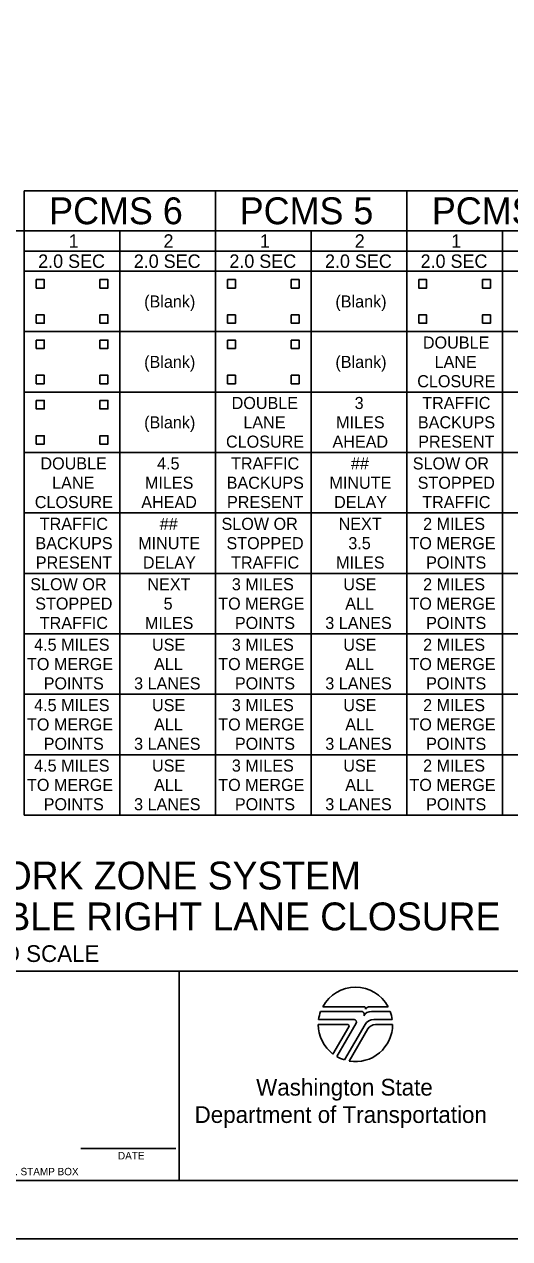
# Model space of a CAD drawing. Extents: x 99999.1 to 100055.7, y 99995 to 100017.5.
# Drawn here: x 100029.47 to 100032.09, y 99999.69 to 100006.22 of the extents above; entities that cross this region are included whole.
import ezdxf

# ---------------------------------------------------------------- set-up
doc = ezdxf.new("R2010")
doc.units = 0
for name, color, linetype in [('SH_DE_DetailHeading1Text', 7, 'Continuous'), ('SH_DE_DetailHeading3Text', 7, 'Continuous'), ('SH_GI_PlotLimits', 7, 'Continuous'), ('SH_GI_SheetBorder', 7, 'Continuous'), ('SH_GI_SheetTextInCells', 7, 'Continuous'), ('SH_GI_WSDOTLogo', 7, 'Continuous'), ('TR_WZ_WorkZoneDetails', 7, 'Continuous'), ('TR_WZ_WorkZoneTextCurrent', 7, 'Continuous')]:
    doc.layers.add(name, color=color, linetype=linetype)

msp = doc.modelspace()

# ---------------------------------------------------------------- linework, layer by layer
at = {"layer": 'SH_GI_PlotLimits'}
msp.add_lwpolyline([(100019.0625, 99999.6875), (100036.0625, 99999.6875), (100036.0625, 100010.6875), (100019.0625, 100010.6875)], close=True, dxfattribs=at)
at = {"layer": 'SH_GI_SheetBorder'}
for p, q in [((100020, 100001.1259), (100035.75, 100001.1259)), ((100030.3089, 100001.1259), (100030.3089, 100000)), ((100029.7797, 100000.1733), (100030.2914, 100000.1733)), ((100020, 100000), (100035.75, 100000))]:
    msp.add_line(p, q, dxfattribs=at)
at = {"layer": 'SH_GI_WSDOTLogo'}
for p, q in [((100031.303, 100000.9354), (100031.0815, 100000.9354)), ((100031.433, 100000.9354), (100031.3351, 100000.9354)), ((100031.059, 100000.8661), (100031.2496, 100000.8661)), ((100031.2894, 100000.9094), (100031.0697, 100000.9094)), ((100031.343, 100000.9094), (100031.3429, 100000.9094)), ((100031.4448, 100000.9094), (100031.343, 100000.9094)), ((100031.3558, 100000.8661), (100031.4555, 100000.8661)), ((100031.0572, 100000.84), (100031.2148, 100000.84)), ((100031.222, 100000.8277), (100031.1364, 100000.6807)), ((100031.261, 100000.8464), (100031.1567, 100000.6672)), ((100031.1989, 100000.6487), (100031.3089, 100000.839)), ((100031.2244, 100000.6428), (100031.3242, 100000.8156)), ((100031.3655, 100000.8394), (100031.4572, 100000.8394))]:
    msp.add_line(p, q, dxfattribs=at)
for centre, radius, start, end in [((100031.2572, 100000.84), 0.2, 28.47865, 151.53204), ((100031.303, 100000.9263), 0.00903, 329.87418, 90.00328), ((100031.3352, 100000.9066), 0.0287, 90.00721, 148.16763), ((100031.2572, 100000.84), 0.2, 159.69598, 172.50569), ((100031.2497, 100000.853), 0.0131, 329.76834, 90), ((100031.2894, 100000.8946), 0.0148, 327.8418, 89.99855), ((100031.3429, 100000.861), 0.0484, 89.99529, 147.82376), ((100031.3558, 100000.8119), 0.0542, 90, 149.99738), ((100031.2572, 100000.84), 0.2, 7.49431, 20.29406), ((100031.2572, 100000.84), 0.2, 179.99864, 232.84327), ((100031.2149, 100000.8318), 0.0082, 329.74356, 90), ((100031.2572, 100000.84), 0.2, 260.54554, 359.80857), ((100031.3654, 100000.7918), 0.0476, 90, 150.05432), ((100031.2572, 100000.84), 0.2, 239.79292, 253.0448)]:
    msp.add_arc(centre, radius, start, end, dxfattribs=at)
at = {"layer": 'TR_WZ_WorkZoneDetails'}
for p, q in [((100029.475, 100005.3241), (100029.475, 100004.9991)), ((100029.475, 100005.3241), (100030.5042, 100005.3241)), ((100030.5042, 100005.3241), (100031.5333, 100005.3241)), ((100030.5042, 100005.3241), (100030.5042, 100004.9991)), ((100031.5333, 100005.3241), (100032.5625, 100005.3241)), ((100031.5333, 100005.3241), (100031.5333, 100004.9991)), ((100031.5333, 100005.3241), (100031.5333, 100004.9991)), ((100029.475, 100005.1075), (100029.475, 100004.9991)), ((100029.9896, 100005.1075), (100029.9896, 100004.9991)), ((100031.0187, 100005.1075), (100031.0187, 100004.9991)), ((100032.0479, 100005.1075), (100032.0479, 100004.9991)), ((100029.475, 100004.9991), (100029.475, 100004.8908)), ((100029.9896, 100004.9991), (100029.9896, 100004.8908)), ((100030.5042, 100004.9991), (100030.5042, 100004.8908)), ((100031.0187, 100004.9991), (100031.0187, 100004.8908)), ((100031.5333, 100004.9991), (100031.5333, 100004.8908)), ((100031.5333, 100004.9991), (100031.5333, 100004.8908)), ((100032.0479, 100004.9991), (100032.0479, 100004.8908)), ((100029.475, 100004.8908), (100029.475, 100004.5658)), ((100030.5042, 100004.8908), (100029.475, 100004.8908)), ((100029.9896, 100004.8908), (100029.9896, 100004.5658)), ((100030.5042, 100004.8908), (100030.5042, 100004.5658)), ((100031.5333, 100004.8908), (100030.5042, 100004.8908)), ((100031.0187, 100004.8908), (100031.0187, 100004.5658)), ((100031.5333, 100004.8908), (100031.5333, 100004.5658)), ((100031.5333, 100004.8908), (100031.5333, 100004.5658)), ((100032.5625, 100004.8908), (100031.5333, 100004.8908)), ((100032.0479, 100004.8908), (100032.0479, 100004.5658)), ((100029.475, 100004.5658), (100029.475, 100004.2408)), ((100030.5042, 100004.5658), (100029.475, 100004.5658)), ((100029.9896, 100004.5658), (100029.9896, 100004.2408)), ((100030.5042, 100004.5658), (100030.5042, 100004.2408)), ((100031.5333, 100004.5658), (100030.5042, 100004.5658)), ((100031.0187, 100004.5658), (100031.0187, 100004.2408)), ((100031.5333, 100004.5658), (100031.5333, 100004.2408)), ((100032.5625, 100004.5658), (100031.5333, 100004.5658)), ((100031.5333, 100004.5658), (100031.5333, 100004.2408)), ((100032.0479, 100004.5658), (100032.0479, 100004.2408)), ((100029.475, 100004.2408), (100029.475, 100003.9158)), ((100030.5042, 100004.2408), (100029.475, 100004.2408)), ((100030.5042, 100004.2408), (100029.475, 100004.2408)), ((100029.9896, 100004.2408), (100029.9896, 100003.9158)), ((100030.5042, 100004.2408), (100030.5042, 100003.9158)), ((100031.5333, 100004.2408), (100030.5042, 100004.2408)), ((100031.5333, 100004.2408), (100030.5042, 100004.2408)), ((100031.0187, 100004.2408), (100031.0187, 100003.9158)), ((100031.5333, 100004.2408), (100031.5333, 100003.9158)), ((100032.5625, 100004.2408), (100031.5333, 100004.2408)), ((100032.5625, 100004.2408), (100031.5333, 100004.2408)), ((100031.5333, 100004.2408), (100031.5333, 100003.9158)), ((100032.0479, 100004.2408), (100032.0479, 100003.9158)), ((100029.475, 100003.9158), (100029.475, 100003.5908)), ((100030.5042, 100003.9158), (100029.475, 100003.9158)), ((100029.9896, 100003.9158), (100029.9896, 100003.5908)), ((100030.5042, 100003.9158), (100030.5042, 100003.5908)), ((100031.5333, 100003.9158), (100030.5042, 100003.9158)), ((100031.0187, 100003.9158), (100031.0187, 100003.5908)), ((100031.5333, 100003.9158), (100031.5333, 100003.5908)), ((100032.5625, 100003.9158), (100031.5333, 100003.9158)), ((100031.5333, 100003.9158), (100031.5333, 100003.5908)), ((100032.0479, 100003.9158), (100032.0479, 100003.5908)), ((100029.475, 100003.5908), (100029.475, 100003.2658)), ((100030.5042, 100003.5908), (100029.475, 100003.5908)), ((100029.9896, 100003.5908), (100029.9896, 100003.2658)), ((100030.5042, 100003.5908), (100030.5042, 100003.2658)), ((100031.5333, 100003.5908), (100030.5042, 100003.5908)), ((100031.0187, 100003.5908), (100031.0187, 100003.2658)), ((100031.5333, 100003.5908), (100031.5333, 100003.2658)), ((100032.5625, 100003.5908), (100031.5333, 100003.5908)), ((100031.5333, 100003.5908), (100031.5333, 100003.2658)), ((100032.0479, 100003.5908), (100032.0479, 100003.2658)), ((100029.475, 100003.2658), (100029.475, 100002.9408)), ((100030.5042, 100003.2658), (100029.475, 100003.2658)), ((100029.9896, 100003.2658), (100029.9896, 100002.9408)), ((100030.5042, 100003.2658), (100030.5042, 100002.9408)), ((100031.5333, 100003.2658), (100030.5042, 100003.2658)), ((100031.0187, 100003.2658), (100031.0187, 100002.9408)), ((100031.5333, 100003.2658), (100031.5333, 100002.9408)), ((100032.5625, 100003.2658), (100031.5333, 100003.2658)), ((100031.5333, 100003.2658), (100031.5333, 100002.9408)), ((100032.0479, 100003.2658), (100032.0479, 100002.9408)), ((100029.475, 100002.9408), (100029.475, 100002.6158)), ((100030.5042, 100002.9408), (100029.475, 100002.9408)), ((100029.9896, 100002.9408), (100029.9896, 100002.6158)), ((100031.5333, 100002.9408), (100030.5042, 100002.9408)), ((100030.5042, 100002.9408), (100030.5042, 100002.6158)), ((100031.0187, 100002.9408), (100031.0187, 100002.6158)), ((100032.5625, 100002.9408), (100031.5333, 100002.9408)), ((100031.5333, 100002.9408), (100031.5333, 100002.6158)), ((100031.5333, 100002.9408), (100031.5333, 100002.6158)), ((100032.0479, 100002.9408), (100032.0479, 100002.6158)), ((100030.5042, 100002.6158), (100029.475, 100002.6158)), ((100029.475, 100002.6158), (100029.475, 100002.2908)), ((100030.5042, 100002.6158), (100029.475, 100002.6158)), ((100029.9896, 100002.6158), (100029.9896, 100002.2908)), ((100031.5333, 100002.6158), (100030.5042, 100002.6158)), ((100031.5333, 100002.6158), (100030.5042, 100002.6158)), ((100030.5042, 100002.6158), (100030.5042, 100002.2908)), ((100031.0187, 100002.6158), (100031.0187, 100002.2908)), ((100032.5625, 100002.6158), (100031.5333, 100002.6158)), ((100032.5625, 100002.6158), (100031.5333, 100002.6158)), ((100031.5333, 100002.6158), (100031.5333, 100002.2908)), ((100031.5333, 100002.6158), (100031.5333, 100002.2908)), ((100032.0479, 100002.6158), (100032.0479, 100002.2908)), ((100029.475, 100002.2908), (100029.475, 100001.9658)), ((100030.5042, 100002.2908), (100029.475, 100002.2908)), ((100029.9896, 100002.2908), (100029.9896, 100001.9658)), ((100030.5042, 100002.2908), (100030.5042, 100001.9658)), ((100031.5333, 100002.2908), (100030.5042, 100002.2908)), ((100031.0187, 100002.2908), (100031.0187, 100001.9658)), ((100031.5333, 100002.2908), (100031.5333, 100001.9658)), ((100031.5333, 100002.2908), (100031.5333, 100001.9658)), ((100032.5625, 100002.2908), (100031.5333, 100002.2908)), ((100032.0479, 100002.2908), (100032.0479, 100001.9658)), ((100030.5042, 100001.9658), (100029.475, 100001.9658)), ((100031.5333, 100001.9658), (100030.5042, 100001.9658)), ((100032.5625, 100001.9658), (100031.5333, 100001.9658))]:
    msp.add_line(p, q, dxfattribs=at)
for points in [[(100028.4458, 100005.1075), (100029.475, 100005.1075)], [(100029.475, 100005.1075), (100030.5042, 100005.1075)], [(100030.5042, 100005.1075), (100031.5333, 100005.1075)], [(100031.5333, 100005.1075), (100032.5625, 100005.1075)], [(100029.475, 100004.9991), (100030.5042, 100004.9991)], [(100030.5042, 100004.9991), (100031.5333, 100004.9991)], [(100031.5333, 100004.9991), (100032.5625, 100004.9991)]]:
    msp.add_lwpolyline(points, dxfattribs=at)
at = {"layer": 'TR_WZ_WorkZoneTextCurrent'}
for points in [[(100029.5393, 100004.8456), (100029.5822, 100004.8456), (100029.5822, 100004.8005), (100029.5393, 100004.8005)], [(100029.8824, 100004.8456), (100029.9253, 100004.8456), (100029.9253, 100004.8005), (100029.8824, 100004.8005)], [(100030.5685, 100004.8456), (100030.6114, 100004.8456), (100030.6114, 100004.8005), (100030.5685, 100004.8005)], [(100030.9115, 100004.8456), (100030.9544, 100004.8456), (100030.9544, 100004.8005), (100030.9115, 100004.8005)], [(100031.5977, 100004.8456), (100031.6405, 100004.8456), (100031.6405, 100004.8005), (100031.5977, 100004.8005)], [(100031.9407, 100004.8456), (100031.9836, 100004.8456), (100031.9836, 100004.8005), (100031.9407, 100004.8005)], [(100029.5393, 100004.6109), (100029.5822, 100004.6109), (100029.5822, 100004.6561), (100029.5393, 100004.6561)], [(100029.8824, 100004.6109), (100029.9253, 100004.6109), (100029.9253, 100004.6561), (100029.8824, 100004.6561)], [(100030.5685, 100004.6109), (100030.6114, 100004.6109), (100030.6114, 100004.6561), (100030.5685, 100004.6561)], [(100030.9115, 100004.6109), (100030.9544, 100004.6109), (100030.9544, 100004.6561), (100030.9115, 100004.6561)], [(100031.5977, 100004.6109), (100031.6405, 100004.6109), (100031.6405, 100004.6561), (100031.5977, 100004.6561)], [(100031.9407, 100004.6109), (100031.9836, 100004.6109), (100031.9836, 100004.6561), (100031.9407, 100004.6561)], [(100029.5393, 100004.5206), (100029.5822, 100004.5206), (100029.5822, 100004.4755), (100029.5393, 100004.4755)], [(100029.8824, 100004.5206), (100029.9253, 100004.5206), (100029.9253, 100004.4755), (100029.8824, 100004.4755)], [(100030.5685, 100004.5206), (100030.6114, 100004.5206), (100030.6114, 100004.4755), (100030.5685, 100004.4755)], [(100030.9115, 100004.5206), (100030.9544, 100004.5206), (100030.9544, 100004.4755), (100030.9115, 100004.4755)], [(100029.5393, 100004.2859), (100029.5822, 100004.2859), (100029.5822, 100004.3311), (100029.5393, 100004.3311)], [(100029.8824, 100004.2859), (100029.9253, 100004.2859), (100029.9253, 100004.3311), (100029.8824, 100004.3311)], [(100030.5685, 100004.2859), (100030.6114, 100004.2859), (100030.6114, 100004.3311), (100030.5685, 100004.3311)], [(100030.9115, 100004.2859), (100030.9544, 100004.2859), (100030.9544, 100004.3311), (100030.9115, 100004.3311)], [(100029.5393, 100004.1956), (100029.5822, 100004.1956), (100029.5822, 100004.1505), (100029.5393, 100004.1505)], [(100029.8824, 100004.1956), (100029.9253, 100004.1956), (100029.9253, 100004.1505), (100029.8824, 100004.1505)], [(100029.5393, 100003.9609), (100029.5822, 100003.9609), (100029.5822, 100004.0061), (100029.5393, 100004.0061)], [(100029.8824, 100003.9609), (100029.9253, 100003.9609), (100029.9253, 100004.0061), (100029.8824, 100004.0061)]]:
    msp.add_lwpolyline(points, close=True, dxfattribs=at)

# ---------------------------------------------------------------- texts
at = {"layer": 'SH_DE_DetailHeading1Text'}
for s, p in [('9-MILE SMART WORK ZONE SYSTEM', (100027.7097, 100001.5658)), ('FREEWAY (3 LANES): DOUBLE RIGHT LANE CLOSURE', (100026.81, 100001.3458))]:
    msp.add_text(s, height=0.15, dxfattribs=at).set_placement(p)
at = {"layer": 'SH_DE_DetailHeading3Text'}
msp.add_text('NOT TO SCALE', height=0.09, dxfattribs=at).set_placement((100028.9969, 100001.1759))
at = {"layer": 'SH_GI_SheetTextInCells'}
for s, height, p in [('Washington State', 0.090072, (100030.7229, 100000.4571)), ('Department of Transportation', 0.090072, (100030.3916, 100000.3101)), ('DATE', 0.04003, (100029.9794, 100000.1141)), ('P.E. STAMP BOX', 0.040032, (100029.339, 100000.0286))]:
    msp.add_text(s, height=height, dxfattribs=at).set_placement(p)
at = {"layer": 'TR_WZ_WorkZoneTextCurrent'}
for s, height, p in [('PCMS 6', 0.14444, (100029.6091, 100005.1436)), ('PCMS 5', 0.14444, (100030.6345, 100005.1436)), ('PCMS 4', 0.14444, (100031.6687, 100005.1436)), ('1', 0.0722, (100029.7142, 100005.0172)), ('2', 0.0722, (100030.2242, 100005.0172)), ('1', 0.0722, (100030.7433, 100005.0172)), ('2', 0.0722, (100031.2534, 100005.0172)), ('1', 0.0722, (100031.7725, 100005.0172)), ('2.0 SEC', 0.07222, (100029.5497, 100004.9088)), ('2.0 SEC', 0.07222, (100030.0643, 100004.9088)), ('2.0 SEC', 0.07222, (100030.5788, 100004.9088)), ('2.0 SEC', 0.07222, (100031.0934, 100004.9088)), ('2.0 SEC', 0.07222, (100031.608, 100004.9088)), ('(Blank)', 0.065, (100030.1202, 100004.6958)), ('(Blank)', 0.065, (100031.1494, 100004.6958)), ('DOUBLE', 0.065, (100031.6203, 100004.4748)), ('(Blank)', 0.065, (100030.1202, 100004.3708)), ('(Blank)', 0.065, (100031.1494, 100004.3708)), ('LANE', 0.065, (100031.6832, 100004.3708)), ('CLOSURE', 0.065, (100031.59, 100004.2668)), ('DOUBLE', 0.065, (100030.5911, 100004.1498)), ('3', 0.065, (100031.253, 100004.1498)), ('TRAFFIC', 0.065, (100031.6168, 100004.1498)), ('(Blank)', 0.065, (100030.1202, 100004.0458)), ('LANE', 0.065, (100030.654, 100004.0458)), ('MILES', 0.065, (100031.1534, 100004.0458)), ('BACKUPS', 0.065, (100031.5935, 100004.0458)), ('CLOSURE', 0.065, (100030.5608, 100003.9418)), ('AHEAD', 0.065, (100031.1337, 100003.9418)), ('PRESENT', 0.065, (100031.5952, 100003.9418)), ('DOUBLE', 0.065, (100029.5619, 100003.8248)), ('4.5', 0.065, (100030.1899, 100003.8248)), ('TRAFFIC', 0.065, (100030.5877, 100003.8248)), ('##', 0.065, (100031.2332, 100003.8248)), ('SLOW OR', 0.065, (100031.5657, 100003.8248)), ('LANE', 0.065, (100029.6248, 100003.7208)), ('MILES', 0.065, (100030.1243, 100003.7208)), ('BACKUPS', 0.065, (100030.5643, 100003.7208)), ('MINUTE', 0.065, (100031.1174, 100003.7208)), ('STOPPED', 0.065, (100031.5923, 100003.7208)), ('CLOSURE', 0.065, (100029.5317, 100003.6168)), ('AHEAD', 0.065, (100030.1045, 100003.6168)), ('PRESENT', 0.065, (100030.566, 100003.6168)), ('DELAY', 0.065, (100031.1424, 100003.6168)), ('TRAFFIC', 0.065, (100031.6168, 100003.6168)), ('TRAFFIC', 0.065, (100029.5585, 100003.4998)), ('##', 0.065, (100030.2041, 100003.4998)), ('SLOW OR', 0.065, (100030.5365, 100003.4998)), ('NEXT', 0.065, (100031.1668, 100003.4998)), ('2 MILES', 0.065, (100031.6214, 100003.4998)), ('BACKUPS', 0.065, (100029.5351, 100003.3958)), ('MINUTE', 0.065, (100030.0882, 100003.3958)), ('STOPPED', 0.065, (100030.5631, 100003.3958)), ('3.5', 0.065, (100031.219, 100003.3958)), ('TO MERGE', 0.065, (100031.5481, 100003.3958)), ('PRESENT', 0.065, (100029.5369, 100003.2918)), ('DELAY', 0.065, (100030.1132, 100003.2918)), ('TRAFFIC', 0.065, (100030.5877, 100003.2918)), ('MILES', 0.065, (100031.1534, 100003.2918)), ('POINTS', 0.065, (100031.6378, 100003.2918)), ('SLOW OR', 0.065, (100029.5073, 100003.1748)), ('NEXT', 0.065, (100030.1377, 100003.1748)), ('3 MILES', 0.065, (100030.5922, 100003.1748)), ('USE', 0.065, (100031.1919, 100003.1748)), ('2 MILES', 0.065, (100031.6214, 100003.1748)), ('STOPPED', 0.065, (100029.534, 100003.0708)), ('5', 0.065, (100030.2249, 100003.0708)), ('TO MERGE', 0.065, (100030.5189, 100003.0708)), ('ALL', 0.065, (100031.2024, 100003.0708)), ('TO MERGE', 0.065, (100031.5481, 100003.0708)), ('TRAFFIC', 0.065, (100029.5585, 100002.9668)), ('MILES', 0.065, (100030.1243, 100002.9668)), ('POINTS', 0.065, (100030.6086, 100002.9668)), ('3 LANES', 0.065, (100031.0951, 100002.9668)), ('POINTS', 0.065, (100031.6378, 100002.9668)), ('4.5 MILES', 0.065, (100029.5281, 100002.8498)), ('USE', 0.065, (100030.1627, 100002.8498)), ('3 MILES', 0.065, (100030.5922, 100002.8498)), ('USE', 0.065, (100031.1919, 100002.8498)), ('2 MILES', 0.065, (100031.6214, 100002.8498)), ('TO MERGE', 0.065, (100029.4897, 100002.7458)), ('ALL', 0.065, (100030.1732, 100002.7458)), ('TO MERGE', 0.065, (100030.5189, 100002.7458)), ('ALL', 0.065, (100031.2024, 100002.7458)), ('TO MERGE', 0.065, (100031.5481, 100002.7458)), ('POINTS', 0.065, (100029.5794, 100002.6418)), ('3 LANES', 0.065, (100030.066, 100002.6418)), ('POINTS', 0.065, (100030.6086, 100002.6418)), ('3 LANES', 0.065, (100031.0951, 100002.6418)), ('POINTS', 0.065, (100031.6378, 100002.6418)), ('4.5 MILES', 0.065, (100029.5281, 100002.5248)), ('USE', 0.065, (100030.1627, 100002.5248)), ('3 MILES', 0.065, (100030.5922, 100002.5248)), ('USE', 0.065, (100031.1919, 100002.5248)), ('2 MILES', 0.065, (100031.6214, 100002.5248)), ('TO MERGE', 0.065, (100029.4897, 100002.4208)), ('ALL', 0.065, (100030.1732, 100002.4208)), ('TO MERGE', 0.065, (100030.5189, 100002.4208)), ('ALL', 0.065, (100031.2024, 100002.4208)), ('TO MERGE', 0.065, (100031.5481, 100002.4208)), ('POINTS', 0.065, (100029.5794, 100002.3168)), ('3 LANES', 0.065, (100030.066, 100002.3168)), ('POINTS', 0.065, (100030.6086, 100002.3168)), ('3 LANES', 0.065, (100031.0951, 100002.3168)), ('POINTS', 0.065, (100031.6378, 100002.3168)), ('4.5 MILES', 0.065, (100029.5281, 100002.1998)), ('USE', 0.065, (100030.1627, 100002.1998)), ('3 MILES', 0.065, (100030.5922, 100002.1998)), ('USE', 0.065, (100031.1919, 100002.1998)), ('2 MILES', 0.065, (100031.6214, 100002.1998)), ('TO MERGE', 0.065, (100029.4897, 100002.0958)), ('TO MERGE', 0.065, (100030.5189, 100002.0958)), ('TO MERGE', 0.065, (100031.5481, 100002.0958)), ('ALL', 0.065, (100030.1732, 100002.0958)), ('ALL', 0.065, (100031.2024, 100002.0958)), ('POINTS', 0.065, (100029.5794, 100001.9918)), ('3 LANES', 0.065, (100030.066, 100001.9918)), ('POINTS', 0.065, (100030.6086, 100001.9918)), ('3 LANES', 0.065, (100031.0951, 100001.9918)), ('POINTS', 0.065, (100031.6378, 100001.9918))]:
    msp.add_text(s, height=height, rotation=360, dxfattribs=at).set_placement(p)

doc.saveas('drawing.dxf')
